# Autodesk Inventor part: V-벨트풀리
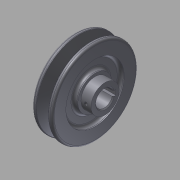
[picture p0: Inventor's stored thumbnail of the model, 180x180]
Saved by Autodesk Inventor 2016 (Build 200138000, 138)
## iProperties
Company: 한국ATC센터
Created: 2014-07
Part Number: V-벨트풀리
Document SubType Name: Modeling
Designer: KYOUNG IL JANG
Density: 7.87 g/cm^3
Material: 강철, 탄소
Mass: 1497.56 g
Surface Area: 466.268 cm^2
Volume: 190.529 cm^3
Appearance: 강철
Author: KYOUNG IL JANG
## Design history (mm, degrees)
sketch "스케치1"
  geometry: L1 (-15, 0)-(15, 0); L2 (-15, 0)-(-15, 17); L3 (-15, 17)-(-11, 17); L4 (-11, 17)-(-11, 29); L5 (-11, 29)-(-15, 29); L6 (-15, 29)-(-15, 42.5); L7 (-15, 42.5)-(-10.976, 42.5); L8 (-10.976, 42.5)-(-7.154, 30); L9 (-7.154, 30)-(-2.846, 30); L10 (-2.846, 30)-(0.976, 42.5); L11 (0.976, 42.5)-(5, 42.5); L12 (5, 42.5)-(5, 29); L13 (5, 29)-(1, 29); L14 (1, 29)-(1, 17); L15 (1, 17)-(5, 17); L16 (5, 17)-(5, 14); L17 (5, 14)-(15, 14); L18 (15, 14)-(15, 0); L19 (-9.6, 38)-(-0.4, 38); 2 further points
  constraints: 38 end point, 11 parallel, 7 collinear, 3 equal length, 3 perpendicular, 2 point on line, 1 coincident, 1 horizontal, 1 midpoint
  dimensions: "d0" = 30 distance of L1.start L1.end; "d1" = 4.5 distance between parallel lines of L7 L19; "d2" = 8 distance between parallel lines of L9 L19; "d3" = 9.2 distance of L19.start L19.end; "d4" = 34 deg angle of L10 L8; "d5" = 20 distance between parallel lines of L12 L6; "d6" = 76 diameter of L19 L1; "d7" = 4 distance of L2.end L3.end; "d8" = 34 diameter of L3 L1; "d9" = 58 diameter of L5 L1; "d10" = 28 diameter of L17 L1
revolve "회전1" sketch "스케치1" stored, may be unused: angle "d11" = 90 deg
sketch "스케치2"
  geometry: L1 (-2.5, 8.124)-(-2.5, 10.8); L2 (-2.5, 10.8)-(2.5, 10.8); L3 (2.5, 10.8)-(2.5, 8.124); A1 r 8.5 centre (0, 0) between (-2.5, 8.124) and (2.5, 8.124); 1 further point
  constraints: 6 end point, 2 parallel, 2 point on circle, 1 centre point, 1 coincident, 1 horizontal, 1 vertical
  dimensions: "d12" = 17 diameter of A1; "d13" = 5 distance of L1.end L2.end; "d14" = 19.3 dimension on A1 L2 (computed from d12)
extrude "돌출1" cut sketch "스케치2" stored distance "d15" = 10; taper "d16" = 0 deg
chamfer "모따기1" distance "d17" = 1; stored, may be unused: second distance "d18" = 2, angle "d19" = 45 deg
node "작업 평면1"
sketch "스케치3"
  geometry: L1 (5, -14)-(5, 14) reference; 3 further points
  constraints: 1 horizontal alignment, 1 midpoint
  dimensions: "d20" = 5 distance from line of L1 point (0, 0)
hole "구멍1" sketch "스케치3" at (0, 0) diameter "d21" = 3.242; stored, may be unused: countersink angle "d25" = 90 deg, drill point angle "d27" = 118 deg; dims "d22" = 6, "d23" = 4, "d24" = 2, "d26" = 8
fillet "모깎기1" dims "d28" = 3, "d29" = 2, "d30" = 0.5, "d31" = 1
node "솔리드1"
